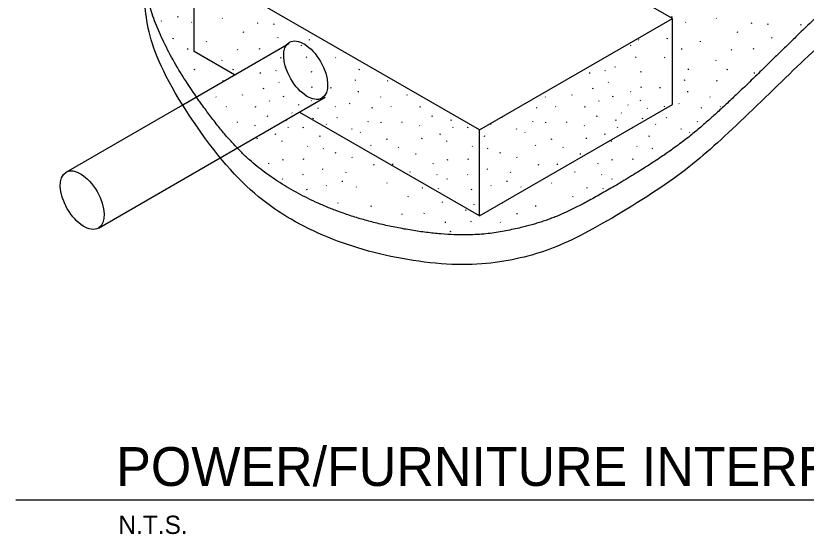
# Model space of a CAD drawing. Extents: x 10309.1 to 10402.7, y 9934 to 9975.2.
# Drawn here: x 10314.21 to 10340.13, y 9935.44 to 9952.45 of the extents above; entities that cross this region are included whole.
import ezdxf

# ---------------------------------------------------------------- set-up
doc = ezdxf.new("R2010")
doc.units = 0
for name, color, linetype in [('G-ANNO-TEXT', 7, 'Continuous'), ('G-DETL-LINE', 7, 'Continuous'), ('G-DETL-OTLN', 7, 'Continuous'), ('G-DETL-PATT', 7, 'Continuous')]:
    doc.layers.add(name, color=color, linetype=linetype)

msp = doc.modelspace()

# ---------------------------------------------------------------- linework, layer by layer
at = {"layer": 'G-ANNO-TEXT'}
msp.add_line((10314.206, 9936.566), (10355.99, 9936.566), dxfattribs=at)
at = {"layer": 'G-DETL-LINE'}
for p, q in [((10319.686, 9949.532), (10323.161, 9951.538)), ((10315.853, 9947.32), (10319.686, 9949.532)), ((10320.913, 9947.792), (10324.353, 9949.778)), ((10316.914, 9945.483), (10320.913, 9947.792))]:
    msp.add_line(p, q, dxfattribs=at)
for centre in [(10323.713, 9950.666), (10316.384, 9946.401)]:
    msp.add_ellipse(centre, major_axis=(0.53, -0.919), ratio=0.531703, dxfattribs=at)
at = {"layer": 'G-DETL-OTLN'}
for p, q in [((10319.532, 9952.414), (10319.503, 9952.408)), ((10335.732, 9952.414), (10335.703, 9952.408)), ((10319.001, 9952.267), (10318.987, 9952.281)), ((10319.982, 9952.228), (10319.968, 9952.242)), ((10320.99, 9952.359), (10320.976, 9952.373)), ((10322.149, 9952.205), (10322.12, 9952.199)), ((10322.67, 9952.168), (10322.679, 9952.196)), ((10336.182, 9952.228), (10336.168, 9952.242)), ((10337.19, 9952.359), (10337.176, 9952.373)), ((10338.349, 9952.205), (10338.32, 9952.199)), ((10338.87, 9952.168), (10338.879, 9952.196)), ((10339.963, 9952.153), (10339.935, 9952.139)), ((10321.676, 9951.907), (10321.685, 9951.935)), ((10337.876, 9951.907), (10337.885, 9951.935)), ((10319.372, 9951.698), (10319.382, 9951.726)), ((10320.459, 9951.594), (10320.468, 9951.622)), ((10322.809, 9951.719), (10322.795, 9951.733)), ((10323.847, 9951.648), (10323.833, 9951.662)), ((10334.647, 9951.648), (10334.633, 9951.662)), ((10335.572, 9951.698), (10335.582, 9951.726)), ((10336.659, 9951.594), (10336.668, 9951.622)), ((10339.009, 9951.719), (10338.995, 9951.733)), ((10319.859, 9951.357), (10319.83, 9951.351)), ((10322.199, 9951.359), (10322.208, 9951.387)), ((10323.58, 9951.48), (10323.552, 9951.466)), ((10334.38, 9951.48), (10334.352, 9951.466)), ((10336.059, 9951.357), (10336.03, 9951.351)), ((10338.399, 9951.359), (10338.408, 9951.387)), ((10321.487, 9951.327), (10321.473, 9951.341)), ((10323.749, 9951.087), (10323.735, 9951.101)), ((10334.549, 9951.087), (10334.535, 9951.101)), ((10337.687, 9951.327), (10337.673, 9951.341)), ((10320.969, 9950.98), (10320.978, 9951.008)), ((10322.908, 9951.07), (10322.879, 9951.063)), ((10324.702, 9951.066), (10324.688, 9951.08)), ((10335.502, 9951.066), (10335.488, 9951.08)), ((10337.169, 9950.98), (10337.178, 9951.008)), ((10320.066, 9950.68), (10320.075, 9950.708)), ((10321.335, 9950.68), (10321.345, 9950.708)), ((10322.241, 9950.573), (10322.212, 9950.567)), ((10322.736, 9950.641), (10322.745, 9950.669)), ((10323.063, 9950.762), (10323.073, 9950.791)), ((10323.909, 9950.602), (10323.918, 9950.63)), ((10325.466, 9950.68), (10325.475, 9950.708)), ((10333.041, 9950.573), (10333.012, 9950.567)), ((10333.536, 9950.641), (10333.545, 9950.669)), ((10333.863, 9950.762), (10333.873, 9950.791)), ((10334.709, 9950.602), (10334.718, 9950.63)), ((10336.266, 9950.68), (10336.275, 9950.708)), ((10337.535, 9950.68), (10337.545, 9950.708)), ((10338.441, 9950.573), (10338.412, 9950.567)), ((10321.011, 9950.312), (10320.982, 9950.306)), ((10325.351, 9950.338), (10325.322, 9950.332)), ((10326.411, 9950.312), (10326.382, 9950.306)), ((10336.151, 9950.338), (10336.122, 9950.332)), ((10337.211, 9950.312), (10337.182, 9950.306)), ((10322.33, 9950.053), (10322.339, 9950.081)), ((10322.848, 9950.257), (10322.834, 9950.271)), ((10323.924, 9950.103), (10323.895, 9950.097)), ((10324.537, 9950.079), (10324.546, 9950.107)), ((10333.13, 9950.053), (10333.139, 9950.081)), ((10333.648, 9950.257), (10333.634, 9950.271)), ((10334.724, 9950.103), (10334.695, 9950.097)), ((10335.337, 9950.079), (10335.346, 9950.107)), ((10320.782, 9949.782), (10320.768, 9949.796)), ((10321.657, 9949.839), (10321.643, 9949.853)), ((10322.985, 9949.796), (10322.994, 9949.824)), ((10323.58, 9949.951), (10323.566, 9949.965)), ((10325.455, 9949.96), (10325.426, 9949.954)), ((10326.182, 9949.782), (10326.168, 9949.796)), ((10327.057, 9949.839), (10327.043, 9949.853)), ((10331.582, 9949.782), (10331.568, 9949.796)), ((10332.457, 9949.839), (10332.443, 9949.853)), ((10333.785, 9949.796), (10333.794, 9949.824)), ((10334.38, 9949.951), (10334.366, 9949.965)), ((10336.255, 9949.96), (10336.226, 9949.954)), ((10336.982, 9949.782), (10336.968, 9949.796)), ((10322.526, 9949.648), (10322.536, 9949.676)), ((10323.904, 9949.656), (10323.89, 9949.67)), ((10325.169, 9949.558), (10325.155, 9949.572)), ((10333.326, 9949.648), (10333.336, 9949.676)), ((10334.704, 9949.656), (10334.69, 9949.67)), ((10335.969, 9949.558), (10335.955, 9949.572)), ((10321.119, 9949.46), (10321.105, 9949.474)), ((10322.068, 9949.453), (10322.078, 9949.481)), ((10323.496, 9949.516), (10323.482, 9949.53)), ((10324.129, 9949.403), (10324.115, 9949.417)), ((10324.691, 9949.46), (10324.677, 9949.474)), ((10325.9, 9949.431), (10325.872, 9949.417)), ((10326.519, 9949.46), (10326.505, 9949.474)), ((10327.468, 9949.453), (10327.478, 9949.481)), ((10331.3, 9949.431), (10331.272, 9949.417)), ((10331.919, 9949.46), (10331.905, 9949.474)), ((10332.868, 9949.453), (10332.878, 9949.481)), ((10334.296, 9949.516), (10334.282, 9949.53)), ((10334.929, 9949.403), (10334.915, 9949.417)), ((10335.491, 9949.46), (10335.477, 9949.474)), ((10336.7, 9949.431), (10336.672, 9949.417)), ((10337.319, 9949.46), (10337.305, 9949.474)), ((10322.461, 9949.149), (10322.471, 9949.177)), ((10323.089, 9949.018), (10323.099, 9949.046)), ((10323.259, 9949.263), (10323.271, 9949.257)), ((10323.271, 9949.257), (10323.276, 9949.25)), ((10323.962, 9949.071), (10323.971, 9949.099)), ((10324.747, 9949.097), (10324.756, 9949.125)), ((10327.861, 9949.149), (10327.871, 9949.177)), ((10328.489, 9949.018), (10328.499, 9949.046)), ((10330.147, 9949.097), (10330.156, 9949.125)), ((10333.261, 9949.149), (10333.271, 9949.177)), ((10333.889, 9949.018), (10333.899, 9949.046)), ((10334.059, 9949.263), (10334.071, 9949.257)), ((10334.071, 9949.257), (10334.076, 9949.25)), ((10334.762, 9949.071), (10334.771, 9949.099)), ((10335.547, 9949.097), (10335.556, 9949.125)), ((10321.482, 9948.96), (10321.453, 9948.954)), ((10322.063, 9948.839), (10322.049, 9948.853)), ((10323.142, 9948.783), (10323.151, 9948.811)), ((10323.634, 9948.779), (10323.643, 9948.807)), ((10324.401, 9948.878), (10324.387, 9948.892)), ((10325.23, 9948.727), (10325.24, 9948.755)), ((10325.767, 9948.966), (10325.777, 9948.994)), ((10326.186, 9948.936), (10326.195, 9948.964)), ((10326.882, 9948.96), (10326.853, 9948.954)), ((10327.463, 9948.839), (10327.449, 9948.853)), ((10328.542, 9948.783), (10328.551, 9948.811)), ((10329.034, 9948.779), (10329.043, 9948.807)), ((10329.801, 9948.878), (10329.787, 9948.892)), ((10330.63, 9948.727), (10330.64, 9948.755)), ((10331.167, 9948.966), (10331.177, 9948.994)), ((10331.586, 9948.936), (10331.595, 9948.964)), ((10332.282, 9948.96), (10332.253, 9948.954)), ((10332.863, 9948.839), (10332.849, 9948.853)), ((10333.942, 9948.783), (10333.951, 9948.811)), ((10334.434, 9948.779), (10334.443, 9948.807)), ((10335.201, 9948.878), (10335.187, 9948.892)), ((10336.03, 9948.727), (10336.04, 9948.755)), ((10336.567, 9948.966), (10336.577, 9948.994)), ((10322.722, 9948.557), (10322.732, 9948.585)), ((10324.183, 9948.492), (10324.193, 9948.52)), ((10325.513, 9948.617), (10325.499, 9948.631)), ((10328.122, 9948.557), (10328.132, 9948.585)), ((10329.583, 9948.492), (10329.593, 9948.52)), ((10330.913, 9948.617), (10330.899, 9948.631)), ((10333.522, 9948.557), (10333.532, 9948.585)), ((10334.983, 9948.492), (10334.993, 9948.52)), ((10336.313, 9948.617), (10336.299, 9948.631)), ((10322.12, 9948.413), (10322.13, 9948.441)), ((10322.947, 9948.333), (10322.919, 9948.327)), ((10326.385, 9948.398), (10326.356, 9948.392)), ((10327.52, 9948.413), (10327.53, 9948.441)), ((10328.347, 9948.333), (10328.319, 9948.327)), ((10331.785, 9948.398), (10331.756, 9948.392)), ((10332.92, 9948.413), (10332.93, 9948.441)), ((10333.747, 9948.333), (10333.719, 9948.327)), ((10323.786, 9948.16), (10323.772, 9948.174)), ((10324.296, 9948.081), (10324.282, 9948.096)), ((10325.867, 9948.186), (10325.853, 9948.2)), ((10326.77, 9948.121), (10326.756, 9948.135)), ((10329.186, 9948.16), (10329.172, 9948.174)), ((10329.696, 9948.081), (10329.682, 9948.096)), ((10331.267, 9948.186), (10331.253, 9948.2)), ((10332.17, 9948.121), (10332.156, 9948.135)), ((10334.586, 9948.16), (10334.572, 9948.174)), ((10335.096, 9948.081), (10335.082, 9948.096)), ((10322.974, 9947.719), (10322.945, 9947.713)), ((10323.647, 9947.734), (10323.656, 9947.763)), ((10324.694, 9947.943), (10324.703, 9947.971)), ((10325.252, 9947.794), (10325.238, 9947.808)), ((10327.34, 9947.915), (10327.311, 9947.909)), ((10328.374, 9947.719), (10328.345, 9947.713)), ((10329.047, 9947.734), (10329.056, 9947.763)), ((10330.094, 9947.943), (10330.103, 9947.971)), ((10330.652, 9947.794), (10330.638, 9947.808)), ((10332.74, 9947.915), (10332.711, 9947.909)), ((10333.774, 9947.719), (10333.745, 9947.713)), ((10334.447, 9947.734), (10334.456, 9947.763)), ((10322.5, 9947.591), (10322.509, 9947.619)), ((10325.95, 9947.552), (10325.96, 9947.58)), ((10326.581, 9947.576), (10326.552, 9947.57)), ((10327.9, 9947.591), (10327.909, 9947.619)), ((10331.35, 9947.552), (10331.36, 9947.58)), ((10331.981, 9947.576), (10331.952, 9947.57)), ((10333.3, 9947.591), (10333.309, 9947.619)), ((10323.637, 9947.23), (10323.622, 9947.244)), ((10324.283, 9947.403), (10324.269, 9947.417)), ((10325.034, 9947.304), (10325.043, 9947.332)), ((10327.141, 9947.317), (10327.15, 9947.345)), ((10328.026, 9947.233), (10328.012, 9947.247)), ((10329.037, 9947.23), (10329.022, 9947.244)), ((10329.683, 9947.403), (10329.669, 9947.417)), ((10330.434, 9947.304), (10330.443, 9947.332)), ((10332.541, 9947.317), (10332.55, 9947.345)), ((10333.426, 9947.233), (10333.412, 9947.247)), ((10322.958, 9947.086), (10322.968, 9947.114)), ((10324.932, 9947.014), (10324.903, 9947.008)), ((10326.39, 9946.959), (10326.376, 9946.973)), ((10328.358, 9947.086), (10328.368, 9947.114)), ((10330.332, 9947.014), (10330.303, 9947.008)), ((10331.79, 9946.959), (10331.776, 9946.973)), ((10333.758, 9947.086), (10333.768, 9947.114)), ((10323.763, 9946.753), (10323.735, 9946.739)), ((10324.401, 9946.867), (10324.387, 9946.881)), ((10325.382, 9946.828), (10325.368, 9946.842)), ((10327.549, 9946.805), (10327.52, 9946.799)), ((10328.07, 9946.768), (10328.079, 9946.796)), ((10329.163, 9946.753), (10329.135, 9946.739)), ((10329.801, 9946.867), (10329.787, 9946.881)), ((10330.782, 9946.828), (10330.768, 9946.842)), ((10332.949, 9946.805), (10332.92, 9946.799)), ((10333.47, 9946.768), (10333.479, 9946.796)), ((10327.076, 9946.507), (10327.085, 9946.535)), ((10332.476, 9946.507), (10332.485, 9946.535)), ((10324.772, 9946.298), (10324.782, 9946.326)), ((10325.859, 9946.194), (10325.868, 9946.222)), ((10328.209, 9946.319), (10328.195, 9946.333)), ((10329.247, 9946.248), (10329.233, 9946.262)), ((10330.172, 9946.298), (10330.182, 9946.326)), ((10331.259, 9946.194), (10331.268, 9946.222)), ((10326.887, 9945.927), (10326.873, 9945.941)), ((10327.599, 9945.959), (10327.608, 9945.987)), ((10328.98, 9946.08), (10328.952, 9946.066)), ((10330.659, 9945.957), (10330.63, 9945.951)), ((10328.308, 9945.67), (10328.279, 9945.663)), ((10329.149, 9945.687), (10329.135, 9945.701)), ((10330.102, 9945.666), (10330.088, 9945.68)), ((10328.463, 9945.362), (10328.473, 9945.391))]:
    msp.add_line(p, q, dxfattribs=at)
at = {"layer": 'G-DETL-PATT'}
for p, q in [((10335.743, 9952.359), (10328.41, 9956.593)), ((10329.411, 9948.703), (10320.058, 9954.103)), ((10320.058, 9951.281), (10320.058, 9954.103)), ((10329.411, 9948.703), (10335.743, 9952.359)), ((10335.743, 9949.537), (10335.743, 9952.359)), ((10321.382, 9950.516), (10320.058, 9951.281)), ((10329.411, 9945.881), (10335.743, 9949.537)), ((10329.411, 9945.881), (10323.52, 9949.282)), ((10329.411, 9945.881), (10329.411, 9948.703))]:
    msp.add_line(p, q, dxfattribs=at)
for points, degree in [([(10351.533, 9957.535), (10351.046, 9956.691), (10349.849, 9956.001), (10346.596, 9954.997), (10344.745, 9954.688), (10341.412, 9953.326), (10339.684, 9951.655), (10337.339, 9949.364), (10335.735, 9948.002), (10332.773, 9946.207), (10331.107, 9945.526), (10328.823, 9945.155), (10325.676, 9945.65), (10323.146, 9946.703), (10321.171, 9948.25), (10318.826, 9951.716), (10318.209, 9954.44), (10318.826, 9956.73), (10319.629, 9958.773), (10319.752, 9960.321), (10319.505, 9961.559), (10319.011, 9962.487)], 2), ([(10351.533, 9956.523), (10351.046, 9955.679), (10349.849, 9954.988), (10346.596, 9953.985), (10344.745, 9953.675), (10341.412, 9952.313), (10339.684, 9950.642), (10337.339, 9948.352), (10335.735, 9946.99), (10332.773, 9945.195), (10331.107, 9944.514), (10328.823, 9944.143), (10325.676, 9944.638), (10323.146, 9945.69), (10321.171, 9947.238), (10318.826, 9950.704), (10318.372, 9952.709), (10318.424, 9953.701), (10318.44, 9953.87)], 3)]:
    msp.add_open_spline(points, degree=degree, dxfattribs=at)

# ---------------------------------------------------------------- texts
at = {"layer": 'G-ANNO-TEXT'}
for s, height, p in [('POWER/FURNITURE INTERFACE DETAIL', 1.275, (10317.5, 9937.022)), ('N.T.S.', 0.6, (10317.571, 9935.447))]:
    msp.add_text(s, height=height, dxfattribs=at).set_placement(p)

doc.saveas('drawing.dxf')
